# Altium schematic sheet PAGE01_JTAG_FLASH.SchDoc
size 381 x 304 mm; SheetNumber: 2; SheetTotal: 28
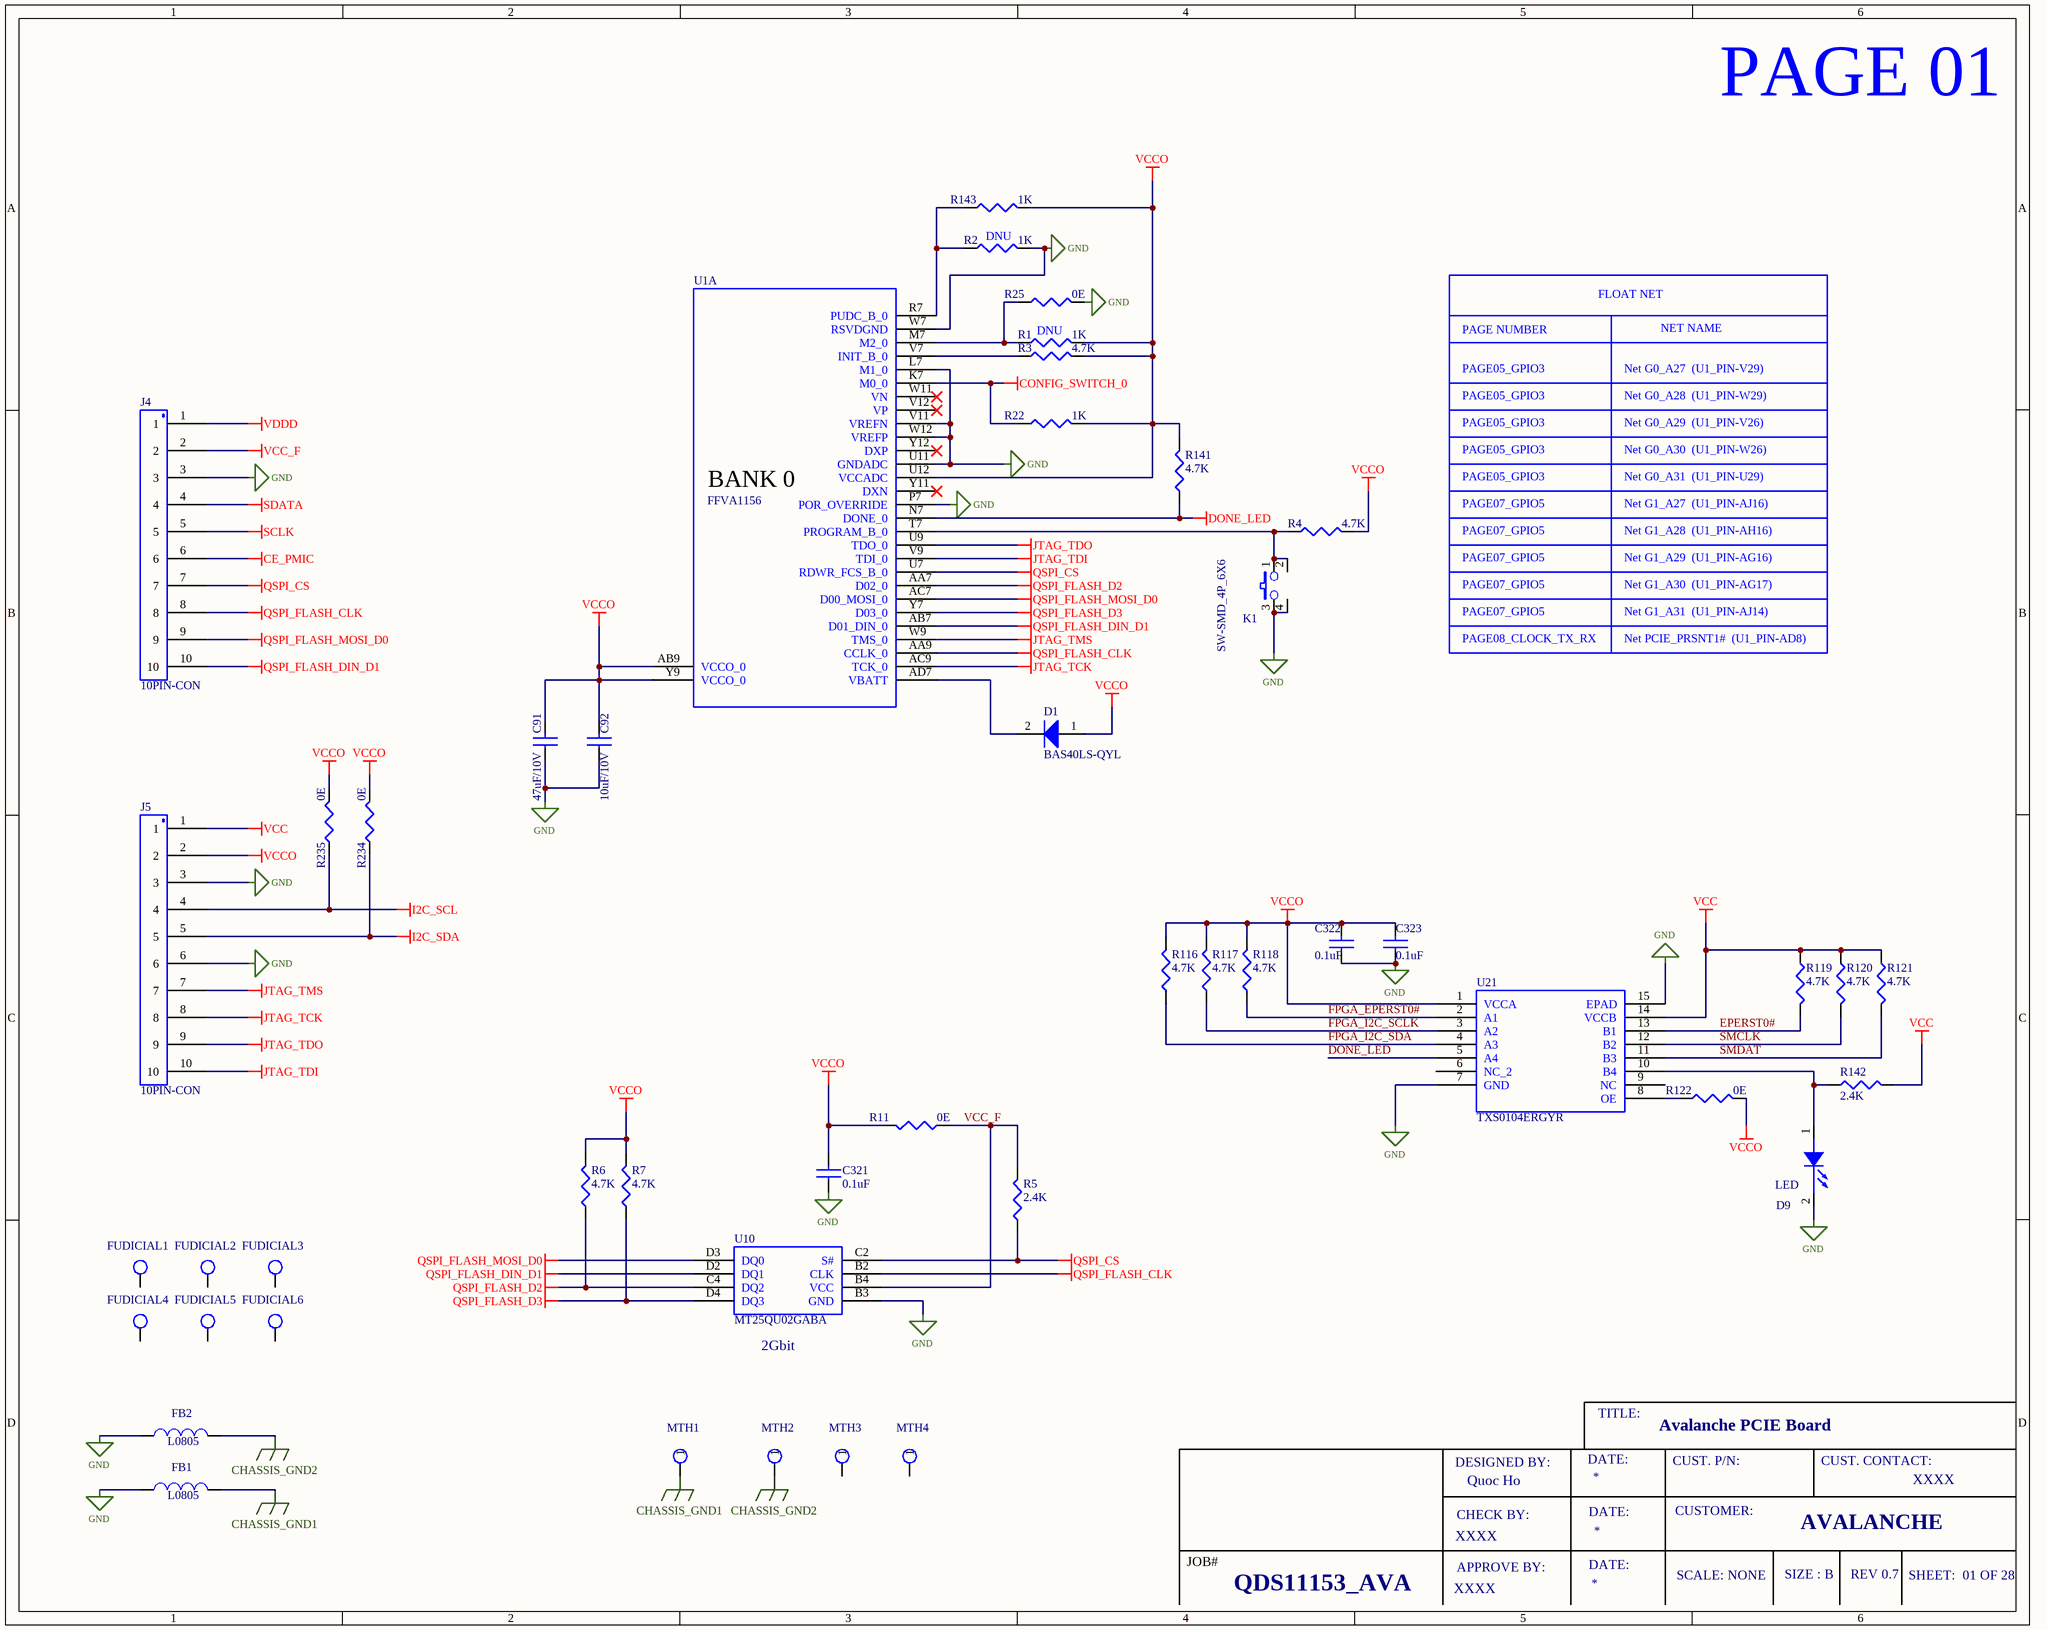
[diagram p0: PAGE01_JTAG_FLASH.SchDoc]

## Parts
C91  47uF/10V  [CN_0805]
C92  10uF/10V  [CN_0402]
C321  0.1uF  [CN_0402]
C322  0.1uF  [CN_0402]
C323  0.1uF  [CN_0402]
D1  BAS40LS-QYL  [BAS40 - SOD523]
D9  LED  [LED_0603]
FB1  L0805  [L0805]
FB2  L0805  [L0805]
FUDICIAL1  FUDICIAL  [FUDICIAL]  (value not drawn)
FUDICIAL2  FUDICIAL  [FUDICIAL]  (value not drawn)
FUDICIAL3  FUDICIAL  [FUDICIAL]  (value not drawn)
FUDICIAL4  FUDICIAL  [FUDICIAL]  (value not drawn)
FUDICIAL5  FUDICIAL  [FUDICIAL]  (value not drawn)
FUDICIAL6  FUDICIAL  [FUDICIAL]  (value not drawn)
J4  10PIN-CON  [68611014422]
J5  10PIN-CON  [68611014422]
K1  SW-SMD_4P_6X6  [SW_PTS815_4P2X3P2X2P5]
MTH1  MTH  [MH_2p3_4MM]  (value not drawn)
MTH2  MTH  [MH_2p3_4MM]  (value not drawn)
MTH3  MTH  [MH_2p3_NPTH _keepout]  (value not drawn)
MTH4  MTH  [MH_2p3_NPTH _keepout]  (value not drawn)
R1  1K  [RN_0402]
R2  1K  [RN_0402]
R3  4.7K  [RN_0402]
R4  4.7K  [RN_0402]
R5  2.4K  [RN_0402]
R6  4.7K  [RN_0402]
R7  4.7K  [RN_0402]
R11  0E  [RN_0402]
R22  1K  [RN_0402]
R25  0E  [RN_0402]
R116  4.7K  [RN_0402]
R117  4.7K  [RN_0402]
R118  4.7K  [RN_0402]
R119  4.7K  [RN_0402]
R120  4.7K  [RN_0402]
R121  4.7K  [RN_0402]
R122  0E  [RN_0402]
R141  4.7K  [RN_0402]
R142  2.4K  [RN_0402]
R143  1K  [RN_0402]
R234  0E  [RN_0402]
R235  0E  [RN_0402]
U1  FFVA1156  [FFVA1156]  (part A of 25)
U10  MT25QU02GABA  [MT25QU02GABA - BGA]
U21  TXS0104ERGYR  [TXS0104ERGYR - VQFN24]

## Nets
CE_PMIC: J4.6
CHASSIS_GND1: FB1.2 MTH1.1
CHASSIS_GND2: FB2.2 MTH2.1
CONFIG_SWITCH_0: R22.1 U1.K7(M0_0)
DONE_LED: R141.1 U1.N7(DONE_0) U21.5(A4)
GND: C91.1 C92.1 C321.1 C322.1 C323.1 D9.2 FB1.1 FB2.1 J4.3 J5.3 J5.6 K1.3 K1.4 R2.2 R25.2 U1.L7(M1_0) U1.P7(POR_OVERRIDE) U1.U11(GNDADC) U1.V11(VREFN) U1.W7(RSVDGND) U1.W12(VREFP) U10.B3(GND) U21.7(GND) U21.15(EPAD)
I2C_SCL: J5.4 R235.1
I2C_SDA: J5.5 R234.1
JTAG_TCK: J5.8 U1.AC9(TCK_0)
JTAG_TDI: J5.10 U1.V9(TDI_0)
JTAG_TDO: J5.9 U1.U9(TDO_0)
JTAG_TMS: J5.7 U1.W9(TMS_0)
QSPI_CS: J4.7 R5.1 U1.U7(RDWR_FCS_B_0) U10.C2(S#)
QSPI_FLASH_CLK: J4.8 U1.AA9(CCLK_0) U10.B2(CLK)
QSPI_FLASH_D2: R6.1 U1.AA7(D02_0) U10.C4(DQ2)
QSPI_FLASH_D3: R7.1 U1.Y7(D03_0) U10.D4(DQ3)
QSPI_FLASH_DIN_D1: J4.10 U1.AB7(D01_DIN_0) U10.D2(DQ1)
QSPI_FLASH_MOSI_D0: J4.9 U1.AC7(D00_MOSI_0) U10.D3(DQ0)
SCLK: J4.5
SDATA: J4.4
VCC: J5.1 R119.2 R120.2 R121.2 R142.1 U21.14(VCCB)
VCC_F: J4.2 R5.2 R11.1 U10.B4(VCC)
VCCO: C91.2 C92.2 C321.2 C322.2 C323.2 D1.1(A) J5.2 R1.2 R3.2 R4.2 R6.2 R7.2 R11.2 R22.2 R116.2 R117.2 R118.2 R122.1 R141.2 R143.2 R234.2 R235.2 U1.AB9(VCCO_0) U1.U12(VCCADC) U1.Y9(VCCO_0) U21.1(VCCA)
VDDD: J4.1
EPERST0#: R119.1 U21.13(B1)
FPGA_EPERST0#: R118.1 U21.2(A1)
FPGA_I2C_SCLK: R117.1 U21.3(A2)
FPGA_I2C_SDA: R116.1 U21.4(A3)
SMCLK: R120.1 U21.12(B2)
SMDAT: R121.1 U21.11(B3)
NetD1_2: D1.2(K) U1.AD7(VBATT)
NetD9_1: D9.1 R142.2 U21.10(B4)
NetK1_1: K1.1 K1.2 R4.1 U1.T7(PROGRAM_B_0)
NetR1_1: R1.1 R25.1 U1.M7(M2_0)
NetR2_1: R2.1 R143.1 U1.R7(PUDC_B_0)
NetR3_1: R3.1 U1.V7(INIT_B_0)
NetR122_2: R122.2 U21.8(OE)

Not connected (* = marked no-connect by the designer): FUDICIAL1 FUDICIAL; FUDICIAL2 FUDICIAL; FUDICIAL3 FUDICIAL; FUDICIAL4 FUDICIAL; FUDICIAL5 FUDICIAL; FUDICIAL6 FUDICIAL; MTH3 1; MTH4 1; U1 V12(VP)* W11(VN)* Y11(DXN)* Y12(DXP)*; U21 6(NC_2) 9(NC)

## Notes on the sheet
- PAGE 01
- (near R2) DNU
- FLOAT NET
- (near R1) DNU
- PAGE NUMBER
- NET NAME
- PAGE05_GPIO3
- Net G0_A27  (U1_PIN-V29)
- Net G0_A28  (U1_PIN-W29)
- Net G0_A29  (U1_PIN-V26)
- (near U1) BANK 0
- Net G0_A30  (U1_PIN-W26)
- Net G0_A31  (U1_PIN-U29)
- PAGE07_GPIO5
- Net G1_A27  (U1_PIN-AJ16)
- Net G1_A28  (U1_PIN-AH16)
- Net G1_A29  (U1_PIN-AG16)
- Net G1_A30  (U1_PIN-AG17)
- Net G1_A31  (U1_PIN-AJ14)
- PAGE08_CLOCK_TX_RX
- Net PCIE_PRSNT1#  (U1_PIN-AD8)
- (near U10) 2Gbit
- TITLE:
- Avalanche PCIE Board
- DESIGNED BY:
- CHECK BY:
- Quoc Ho
- DATE:
- CUST. P/N:
- CUSTOMER:
- CUST. CONTACT:
- XXXX
- JOB#
- APPROVE BY:
- SCALE: NONE
- SIZE : B
- AVALANCHE
- REV 0.7
- SHEET:  01 OF 28
- QDS11153_AVA

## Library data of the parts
C91 = CAP: CAP CER 47UF 10V X5R 0805; Manufacturer Part Number: GRM21BR61A476ME15K; Manufacturer: Murata Electronics
C92 = CAP: CAP CER 10UF 10V X5R 0402; Manufacturer: Murata Electronics; Manufacturer Part Number: GRM155R61A106ME11D
C321-C323 = CAP: CAP CER 0.1UF 50V X7R 0402; Manufacturer Part Number: GCM155R71H104KE02J; Manufacturer: Murata Electronics
D1 = BAS40: DIODE SCHOTTKY 40V 200MA SOD523; Manufacturer Part Number: BAS40X-TP; Manufacturer: Micro Commercial Co; Reverse Recovery Time-Max: 1ns; Power Dissipation: 500mW
D9 = LED: LED GREEN CLEAR SMD; Manufacturer Part Number: LTST-C191KGKT; Manufacturer: Lite-On Inc.
FB1 FB2 = INDUCTOR: FERRITE BEAD 110 OHM 0805 1LN; Manufacturer Part Number: BLM21SP111SZ1D; Manufacturer: Murata Electronics
J4 J5 = 10PIN-CON: CONN FPC BOTTOM 10POS 1MM R/A; Manufacturer: Würth Elektronik
K1 = SW PUSH-S_2: SWITCH TACTILE SPST-NO 0.05A 12V; Manufacturer: C&K; Manufacturer Part Number: PTS815 SJK 250 SMTR LFS
MTH1-MTH4 = FUDICIAL
R1 R2 R22 R143 = RES: RES 1K OHM 1% 1/16W 0402; Manufacturer Part Number: RC0402FR-131KL; Manufacturer: YAGEO
R3 R4 R6 R7 R116-R121 R141 = RES: RES 4.7K OHM 1% 1/16W 0402; Manufacturer Part Number: RC0402FR-134K7L; Manufacturer: YAGEO
R5 R142 = RES: RES 2.4K OHM 1% 1/16W 0402; Manufacturer Part Number: RC0402FR-072K4L; Manufacturer: YAGEO
R11 R25 R122 = RES: RES 0 OHM JUMPER 1/16W 0402; Manufacturer Part Number: RC0402FR-070RL; Manufacturer: YAGEO
R234 = RES: RES 0 OHM JUMPER 1/16W 0402; Manufacturer Part Number: RC0402FR-070RL_DNI; Manufacturer: YAGEO
R235 = RES: RES 0 OHM JUMPER 1/16W 0402; Manufacturer: YAGEO; Manufacturer Part Number: RC0402FR-070RL_DNI
U1 = FFVA1156: IC FPGA 516 I/O 1156FCBGA; Manufacturer Part Number: XCKU15P-1FFVA1156E; Manufacturer: AMD
U10 = MT25QU02GABA: IC FLASH 256MBIT SPI 24TPBGA; Manufacturer Part Number: MT25QU256ABA8E12-0AAT; Manufacturer: Micron Technology Inc.
U21 = TXS0104ERGYR: IC TRANSLTR BIDIRECTIONAL 14VQFN; Manufacturer: Texas Instruments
